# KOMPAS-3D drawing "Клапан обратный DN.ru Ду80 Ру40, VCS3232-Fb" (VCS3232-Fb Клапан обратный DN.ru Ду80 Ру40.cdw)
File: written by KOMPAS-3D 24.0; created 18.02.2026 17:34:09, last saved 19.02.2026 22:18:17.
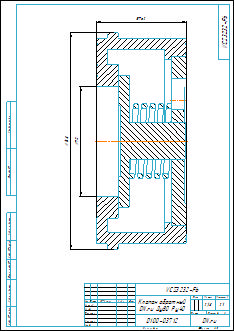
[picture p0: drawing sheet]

Document properties: v313: 1; D: 58; d: 20; a: 1; L: 28; Артикул: D100-03712; Автор: R2D2; Форматы листов документа: A3; Полное имя файла: VCS3232-Fb Клапан обратный DN.ru Ду80 Ру40.m3d; Масса: 2.18; Наименование: Клапан обратный DN.ru Ду80 Ру40; Количество листов документа: 1; Примечание: D100-03712

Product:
- Body: Тело 1  | qty 1
    Масса: 2.07873
- Body: Тело 2  | qty 1
    Масса: 0.88072
- Part/product: Клапан обратный DN.ru Ду80 Ру40  | designation VCS3232-Fb
    Масса: 2.18
    Примечание: D100-03712
    additional columns: 1; D100-03712

Views: Вид 1, Местный разрез 1, Справа
Referenced files in E:\Работа\Зайцев\VCS3232-Fb Клапан обратный DN.ru Ду15-100\DN32\: VCS3232-Fb Клапан обратный DN.ru Ду32 Ру40.m3d
Referenced files in E:\Работа\Зайцев\VCS3232-Fb Клапан обратный DN.ru Ду15-100\DN25\: VCS3232-Fb Клапан обратный DN.ru Ду25 Ру40.m3d
Referenced files in E:\Работа\Зайцев\VCS3232-Fb Клапан обратный DN.ru Ду15-100\DN80\: VCS3232-Fb Клапан обратный DN.ru Ду80 Ру40.m3d
Referenced files in E:\Работа\Зайцев\Для компаса\: чертеж DN.ru.cdt
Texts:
  VCS3232-Fb
  чертеж DN.ru.cdt
  Клапан обратный
  DN.ru Ду80 Ру40
  prop
  Клапан обратный DN.ru Ду80 Ру40
  VCS3232-Fb Клапан обратный DN.ru Ду80 Ру40
Dimensions and other numbers on the sheet: 0; 3; 2; 4; 70; 138; 57±2; 6; 2:1; 1; 2,18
